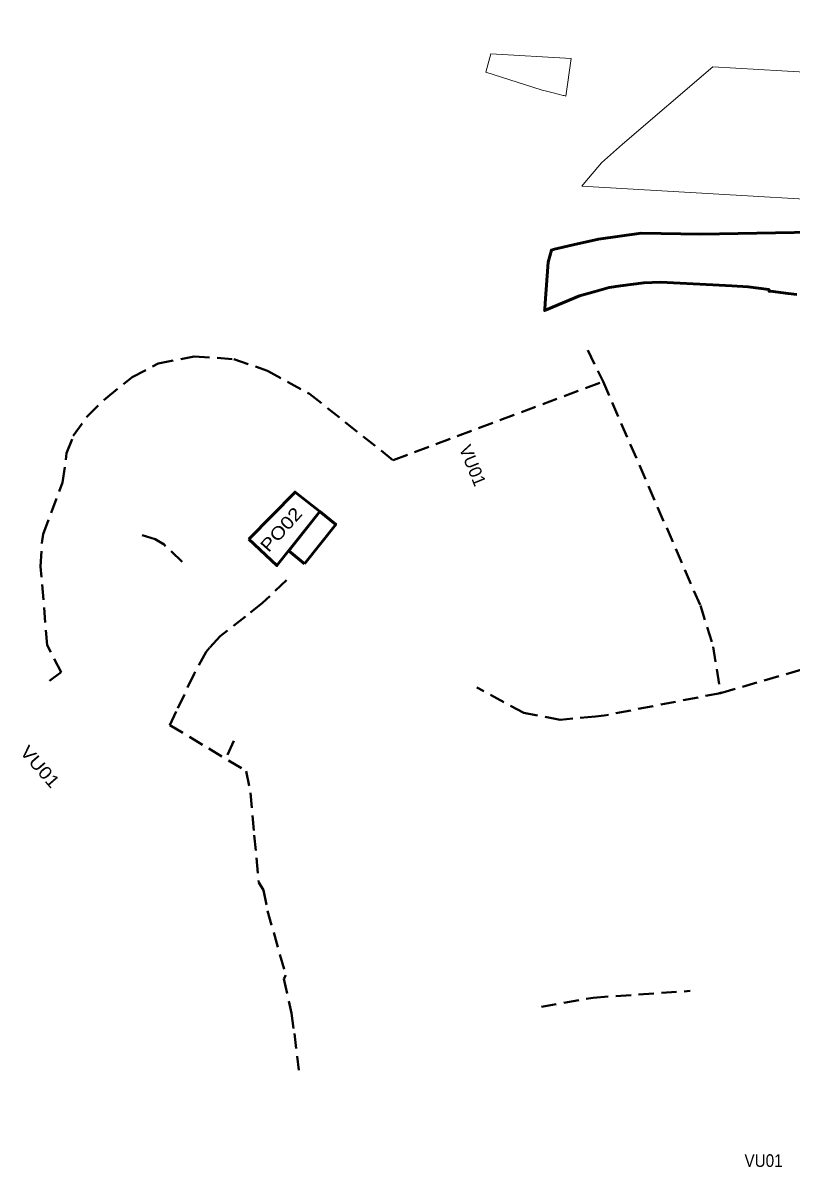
# Model space of a CAD drawing. Extents: x -650145 to -642675, y -1074338 to -1066724.
# Drawn here: x -650145 to -648933, y -1070645 to -1068839 of the extents above; entities that cross this region are included whole.
import ezdxf

# ---------------------------------------------------------------- set-up
doc = ezdxf.new("R2010")
doc.units = 0
doc.header["$LTSCALE"] = 8
doc.linetypes.add('MEDIUM_DASHED', pattern=[4.5, 3, -1.5])
for name, color, linetype, lineweight in [('12', 7, 'MEDIUM_DASHED', 40), ('20', 7, 'Continuous', 13), ('45', 7, 'Continuous', 53), ('46', 7, 'Continuous', 53)]:
    doc.layers.add(name, color=color, linetype=linetype, lineweight=lineweight)
doc.layers.add('2', color=7, linetype='Continuous')
doc.layers.add('5', color=7, linetype='Continuous')

msp = doc.modelspace()

# ---------------------------------------------------------------- linework, layer by layer
at = {"layer": '12'}
for p, q in [((-649561.229, -1069529.679), (-649230.09, -1069405.382)), ((-649812.401, -1069972.556), (-649825.281, -1070000.693))]:
    msp.add_line(p, q, dxfattribs=at)
for points in [[(-649253.852, -1069356.119), (-649230.09, -1069405.382), (-649076.593, -1069758.743), (-649056.232, -1069823.932), (-649044.908, -1069897.057), (-649228.331, -1069932.561), (-649242.081, -1069934.228), (-649297.984, -1069939.047), (-649354.851, -1069928.445), (-649429.2, -1069888.2)], [(-650103.474, -1069877.787), (-650084.938, -1069864.261), (-650106.91, -1069821.516), (-650117.539, -1069697.081), (-650115.437, -1069660.575), (-650113.146, -1069646.371), (-650082.659, -1069564.521), (-650076.339, -1069518.627), (-650065.774, -1069491.142), (-650043.673, -1069460), (-650014.541, -1069431.96), (-649972.852, -1069398.452), (-649931.689, -1069377.161), (-649874.912, -1069365.805), (-649812.457, -1069370.063), (-649759.229, -1069388.516), (-649693.075, -1069424.839), (-649561.229, -1069529.679)], [(-649894.276, -1069689.929), (-649922.552, -1069662.785), (-649936.52, -1069654.039), (-649956.998, -1069647.787)], [(-649729.723, -1069719.048), (-649767.23, -1069754.779), (-649794.247, -1069776.092), (-649834.299, -1069807.359), (-649851.029, -1069825.755), (-649856.254, -1069832.159), (-649875.133, -1069866.696), (-649903.303, -1069925.944), (-649913.581, -1069947.56), (-649793.063, -1070020.079), (-649786.071, -1070054.229), (-649780.314, -1070121.295), (-649773.322, -1070195.767), (-649766.003, -1070207.927), (-649759.422, -1070240.431), (-649730.633, -1070342.059), (-649733.512, -1070347.819), (-649721.595, -1070402.368), (-649717.071, -1070434.049), (-649709.95, -1070492.08)], [(-649044.908, -1069897.057), (-648493.206, -1069738.027), (-648473.126, -1069807.804), (-648452.457, -1069825.52), (-648407.58, -1069817.388), (-648283.564, -1069782.827)], [(-649327.442, -1070392.02), (-649245.779, -1070377.706), (-649092.777, -1070367.093)]]:
    msp.add_lwpolyline(points, dxfattribs=at)
at = {"layer": '20'}
for points in [[(-645696.222, -1068110.701), (-645999.704, -1068380.07), (-646264.963, -1068537.869), (-646558.558, -1068712.401), (-646840.473, -1068879.978), (-647082.853, -1069024.029), (-647392.269, -1069006.02), (-647721.495, -1068986.72), (-648010.52, -1068969.88), (-648329.902, -1068951.251), (-648639.277, -1068933.111), (-648948.071, -1068915.071), (-649057.05, -1068908.69), (-649199.47, -1069030.73), (-649232.77, -1069060.44), (-649258.79, -1069091.17), (-649263.719, -1069096.97)], [(-649263.719, -1069096.97), (-648650.963, -1069132.769), (-648341.578, -1069150.909), (-648022.16, -1069169.54), (-647733.165, -1069186.38), (-647403.931, -1069205.68), (-647033.327, -1069227.251), (-646738.287, -1069051.902)]]:
    msp.add_lwpolyline(points, dxfattribs=at)
msp.add_lwpolyline([(-649319.15, -1068947.37), (-649308.65, -1068950), (-649293.04, -1068953.81), (-649291.32, -1068954.23), (-649288.57, -1068954.9), (-649280.244, -1068895.622), (-649407.325, -1068888.181), (-649415.09, -1068917.1), (-649327.68, -1068945.23), (-649326.13, -1068945.72)], close=True, dxfattribs=at)
at = {"layer": '45'}
msp.add_lwpolyline([(-648781.015, -1069167.44), (-649076.02, -1069172.683), (-649169.781, -1069171.432), (-649237.512, -1069180.731), (-649277.021, -1069189.913), (-649306.455, -1069196.754), (-649311.633, -1069197.958), (-649316.47, -1069216.91), (-649321.32, -1069281.47), (-649322.09, -1069291.73), (-649322.22, -1069293.54), (-649319.72, -1069292.47), (-649267.5, -1069270.41), (-649242.5, -1069263.3), (-649220.18, -1069257.03), (-649202.63, -1069254.4), (-649165.62, -1069249.43), (-649139.63, -1069248.73), (-649056.95, -1069252.55), (-649026.955, -1069254.366), (-649001.3, -1069255.92), (-648968.49, -1069260.36), (-648968.05, -1069263.06), (-648965.8, -1069262.75), (-648937.91, -1069266.51), (-648924.13, -1069268.21)], dxfattribs=at)
at = {"layer": '46'}
for points in [[(-649788.91, -1069654.4), (-649744.517, -1069695.746), (-649677.124, -1069610.681), (-649715.908, -1069579.804)], [(-649701.211, -1069692.826), (-649651.773, -1069630.879), (-649677.124, -1069610.681), (-649726.033, -1069672.415)]]:
    msp.add_lwpolyline(points, close=True, dxfattribs=at)

# ---------------------------------------------------------------- texts
at = {"layer": '2'}
msp.add_text('VU01', height=20, rotation=292.277, dxfattribs=at).set_placement((-649457.739, -1069510.652))
at = {"layer": '2', "width": 1.15}
msp.add_text('VU01', height=20, rotation=310.892, dxfattribs=at).set_placement((-650151.079, -1069990.662))
at = {"layer": '2', "width": 0.9}
msp.add_text('VU01', height=20, dxfattribs=at).set_placement((-649006.975, -1070644.798))
at = {"layer": '5', "width": 1.2}
msp.add_text('PO02', height=20, rotation=48.242, dxfattribs=at).set_placement((-649757.728, -1069676.189))

doc.saveas('drawing.dxf')
